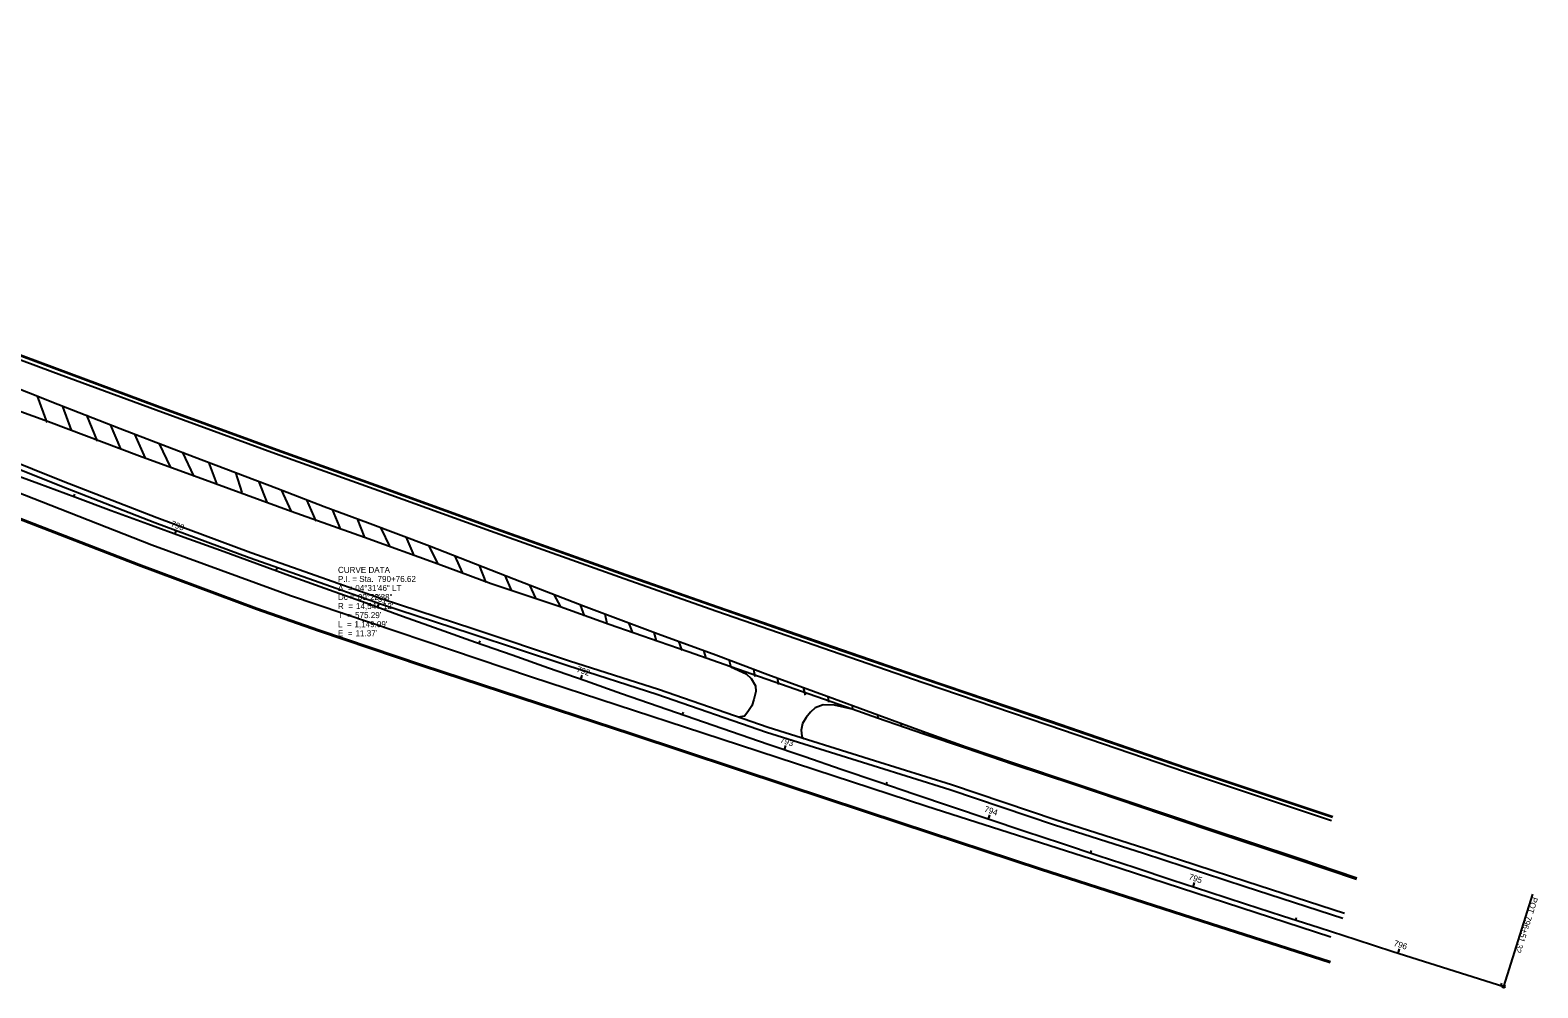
# Model space of a CAD drawing. Extents: x 2349621 to 2352073, y 625611 to 626553.
# Drawn here: x 2351373 to 2352073, y 625611 to 626056 of the extents above; entities that cross this region are included whole.
import ezdxf

# ---------------------------------------------------------------- set-up
doc = ezdxf.new("R2010")
doc.units = 0
for name, color, linetype in [('PM_X_Edge_Line', 7, 'Continuous'), ('PM_X_Lane_Line', 7, 'Continuous'), ('PV_X_Curb', 7, 'Continuous'), ('PV_X_EOP', 7, 'Continuous'), ('RW_X_CL', 7, 'Continuous'), ('RW_X_CL_1000_Cardinal_Points', 7, 'Continuous'), ('RW_X_CL_1000_Curve_Data', 7, 'Continuous'), ('RW_X_CL_1000_Stations', 7, 'Continuous'), ('RW_X_CL_100_Cardinal_Points', 7, 'Continuous'), ('RW_X_CL_100_Curve_Data', 7, 'Continuous'), ('RW_X_CL_100_Stations', 7, 'Continuous'), ('RW_X_CL_500_Cardinal_Points', 7, 'Continuous'), ('RW_X_CL_500_Curve_Data', 7, 'Continuous'), ('RW_X_CL_500_Stations', 7, 'Continuous')]:
    doc.layers.add(name, color=color, linetype=linetype)

msp = doc.modelspace()

# ---------------------------------------------------------------- linework, layer by layer
at = {"layer": 'PM_X_Edge_Line'}
for p, q in [((2351376.36, 625885.73), (2351380.84, 625873.57)), ((2351388.04, 625880.99), (2351392.18, 625870)), ((2351399.17, 625876.89), (2351404.23, 625864.91)), ((2351410.14, 625872.65), (2351414.94, 625861.28)), ((2351421.47, 625868.05), (2351426.41, 625857.03)), ((2351432.72, 625864), (2351438.15, 625852.68)), ((2351443.65, 625859.86), (2351448.97, 625848.49)), ((2351455.76, 625855.15), (2351459.52, 625845.23)), ((2351468.31, 625850.27), (2351471.33, 625841.06)), ((2351479.08, 625846.31), (2351482.87, 625836.48)), ((2351489.61, 625842.24), (2351494.17, 625832.3)), ((2351501.33, 625837.59), (2351505.6, 625827.67)), ((2351513.12, 625833.11), (2351517.13, 625823.81)), ((2351524.78, 625828.8), (2351528.25, 625820.22)), ((2351535.83, 625824.52), (2351539.96, 625815.78)), ((2351547.42, 625820.43), (2351551.12, 625811.83)), ((2351558.03, 625816.33), (2351562.27, 625807.85)), ((2351570.16, 625811.41), (2351573.43, 625803.84)), ((2351581.46, 625807.23), (2351584.55, 625799.22)), ((2351593.27, 625802.55), (2351596.23, 625795.72)), ((2351604.81, 625797.97), (2351607.53, 625792.05)), ((2351616.08, 625793.71), (2351619.08, 625787.98)), ((2351628.32, 625788.84), (2351630.09, 625783.85)), ((2351639.62, 625784.73), (2351640.66, 625780.21)), ((2351650.79, 625780.26), (2351652.47, 625775.89)), ((2351662.44, 625776.12), (2351663.45, 625772.26)), ((2351673.87, 625772.01), (2351675.4, 625767.7)), ((2351685.5, 625767.67), (2351686.61, 625764.06)), ((2351697.43, 625763.07), (2351697.97, 625760.51)), ((2351708.69, 625758.97), (2351709.31, 625755.61)), ((2351719.62, 625754.94), (2351720.29, 625751.98)), ((2351731.66, 625750.47), (2351732.57, 625746.94)), ((2351743.22, 625746.25), (2351743.45, 625743.64)), ((2351754.44, 625742.14), (2351754.65, 625740.35)), ((2351766.12, 625737.97), (2351766.34, 625736.14)), ((2351776.99, 625733.9), (2351777.4, 625732.36)), ((2351787.52, 625730.01), (2351787.61, 625728.96))]:
    msp.add_line(p, q, dxfattribs=at)
for points in [[(2350977.47, 626053.74), (2351016.31, 626038.35), (2351064.02, 626019.46), (2351106.89, 626002.49), (2351147.94, 625986.36), (2351202.99, 625965.26), (2351234.48, 625953.25), (2351287.27, 625933.36), (2351341.06, 625912.89), (2351383.66, 625897.13), (2351431.5, 625879.43), (2351486.97, 625859.09), (2351534.91, 625841.93), (2351586.59, 625823.19), (2351648.67, 625801.11), (2351691.59, 625785.98), (2351744.85, 625767.54), (2351787.37, 625752.87), (2351845.28, 625733.19), (2351909.09, 625711.34), (2351976.75, 625688.75)], [(2350963.74, 626014.89), (2351032.32, 625987.17), (2351095.71, 625962.07), (2351152.54, 625939.23), (2351209.68, 625916.15), (2351265.03, 625893.7), (2351303.58, 625877.76), (2351345.44, 625860.89), (2351387.6, 625843.99), (2351430.99, 625827.11), (2351474.75, 625810.9), (2351502.4, 625801.12), (2351535.69, 625789.35), (2351577.68, 625775.6), (2351622.58, 625760.66), (2351663.85, 625747.4), (2351714.74, 625729.84), (2351764.19, 625714.28), (2351799.77, 625703.13), (2351848.31, 625686.82), (2351889.58, 625673.56), (2351936.76, 625658.21), (2351982.15, 625643.49)], [(2351976.42, 625623.21), (2351920.83, 625640.97), (2351841.95, 625666.41), (2351777.12, 625687.69), (2351724.25, 625705.24), (2351652.33, 625728.98), (2351591.84, 625748.83), (2351555.08, 625760.87), (2351507.03, 625777.09), (2351478.29, 625787.21), (2351423.53, 625807.58), (2351365.19, 625830.22), (2351304.85, 625854.49), (2351247.93, 625877.37), (2351203.89, 625894.92), (2351143.43, 625919.65), (2351117.74, 625929.97), (2351079.36, 625945.33), (2351042.9, 625960.12), (2351003.33, 625976.06), (2350965.81, 625991.28), (2350956.45, 625995.04)], [(2351344.1, 625898.66), (2351385.94, 625881.99), (2351414.84, 625870.78), (2351449.22, 625857.66), (2351487.58, 625843.02), (2351509.43, 625834.57), (2351529.62, 625827.1), (2351558.41, 625816.34), (2351597.42, 625801.03), (2351629.84, 625788.39), (2351664.5, 625775.46), (2351691.21, 625765.65), (2351715.27, 625756.61), (2351746.28, 625745.26), (2351766.86, 625737.73), (2351788.72, 625729.58), (2351807.32, 625722.96), (2351829.82, 625715.37), (2351857.47, 625706.1), (2351919.67, 625685.17), (2351961.16, 625671.41), (2351988.6, 625662.13)]]:
    msp.add_lwpolyline(points, dxfattribs=at)
at = {"layer": 'PM_X_Lane_Line'}
msp.add_lwpolyline([(2350960.41, 626005.5), (2351002.64, 625988.3), (2351066, 625962.88), (2351136.34, 625934.22), (2351210.8, 625903.65), (2351315.64, 625861.8), (2351357.25, 625845.01), (2351429.58, 625816.81), (2351493.91, 625793.24), (2351605.6, 625755.44), (2351685.16, 625729.5), (2351789.05, 625695.46), (2351865.04, 625671.13), (2351976.54, 625634.71)], dxfattribs=at)
at = {"layer": 'PV_X_Curb'}
msp.add_lwpolyline([(2350978.14, 626055.68), (2351017.07, 626040.25), (2351064.77, 626021.37), (2351107.64, 626004.39), (2351148.68, 625988.27), (2351203.72, 625967.18), (2351235.21, 625955.17), (2351288, 625935.28), (2351341.78, 625914.81), (2351384.37, 625899.05), (2351432.2, 625881.35), (2351487.67, 625861.02), (2351535.61, 625843.86), (2351587.29, 625825.12), (2351649.36, 625803.04), (2351692.27, 625787.92), (2351745.52, 625769.48), (2351788.03, 625754.81), (2351845.94, 625735.13), (2351909.74, 625713.28), (2351977.4, 625690.7)], dxfattribs=at)
at = {"layer": 'PV_X_EOP'}
for points in [[(2351977.24, 625690.22), (2351909.58, 625712.81), (2351845.78, 625734.65), (2351787.87, 625754.34), (2351745.36, 625769.01), (2351692.1, 625787.45), (2351649.19, 625802.57), (2351587.12, 625824.65), (2351535.44, 625843.39), (2351487.5, 625860.55), (2351432.03, 625880.88), (2351384.2, 625898.58), (2351341.6, 625914.34), (2351287.82, 625934.81), (2351235.03, 625954.7), (2351203.54, 625966.71), (2351148.5, 625987.81), (2351107.45, 626003.93), (2351064.59, 626020.91), (2351016.88, 626039.79), (2350977.96, 626055.22)], [(2351982.85, 625645.63), (2351937.46, 625660.36), (2351890.28, 625675.71), (2351849.01, 625688.96), (2351800.47, 625705.27), (2351764.87, 625716.44), (2351715.44, 625731.98), (2351664.57, 625749.54), (2351623.28, 625762.81), (2351578.39, 625777.74), (2351536.41, 625791.49), (2351503.15, 625803.24), (2351475.52, 625813.02), (2351431.79, 625829.22), (2351388.43, 625846.09), (2351346.28, 625862.98), (2351304.44, 625879.85), (2351265.89, 625895.79), (2351210.53, 625918.24), (2351153.38, 625941.32), (2351096.55, 625964.17), (2351033.16, 625989.26), (2350964.49, 626017.02)], [(2351976.27, 625622.73), (2351920.68, 625640.49), (2351841.8, 625665.93), (2351776.97, 625687.21), (2351724.09, 625704.77), (2351652.18, 625728.51), (2351591.68, 625748.36), (2351554.93, 625760.4), (2351506.86, 625776.62), (2351478.12, 625786.74), (2351423.35, 625807.11), (2351365, 625829.75), (2351304.66, 625854.02), (2351247.74, 625876.9), (2351203.71, 625894.46), (2351143.24, 625919.19), (2351117.55, 625929.5), (2351079.17, 625944.86), (2351042.71, 625959.65), (2351003.14, 625975.6), (2350965.62, 625990.82), (2350956.27, 625994.57)], [(2351988.37, 625661.45), (2351960.93, 625670.74), (2351919.45, 625684.49), (2351857.24, 625705.43), (2351829.59, 625714.69), (2351807.08, 625722.29), (2351787.66, 625728.93), (2351766.19, 625736.23), (2351754.38, 625740.42), (2351698.18, 625760.06), (2351678.43, 625767), (2351664.88, 625771.73), (2351641.72, 625779.77), (2351618.91, 625787.9), (2351586.99, 625798.6), (2351562.33, 625807.73), (2351528.25, 625820.2), (2351494.14, 625832.28), (2351459.11, 625845.08), (2351423.86, 625857.97), (2351381.54, 625873.89), (2351346.84, 625886.35)], [(2351698.18, 625760.06), (2351705.3, 625756.82), (2351707.63, 625754.77), (2351709.58, 625751.23), (2351709.69, 625748.61), (2351708.88, 625744.9), (2351707.89, 625742.03), (2351706.07, 625739.26), (2351704.43, 625737.23), (2351701.75, 625736.68)], [(2351754.38, 625740.42), (2351746.22, 625742.39), (2351740.94, 625742.49), (2351737.35, 625741.14), (2351735.18, 625739.09), (2351733.13, 625736.65), (2351731.37, 625733.73), (2351730.85, 625730.73), (2351731.14, 625727.86), (2351732.08, 625726.71)]]:
    msp.add_lwpolyline(points, dxfattribs=at)
at = {"layer": 'RW_X_CL'}
msp.add_arc((2356442.68, 639481.86), 14547.12, 247.922783, 252.452173, dxfattribs=at)
at = {"layer": 'RW_X_CL_1000_Cardinal_Points'}
msp.add_line((2352056.7, 625611.68), (2352070.26, 625654.59), dxfattribs=at)
msp.add_circle((2352056.7, 625611.68), 0.6, dxfattribs=at)
at = {"layer": 'RW_X_CL_1000_Stations'}
for p, q in [((2351440.29, 625821.89), (2351440.98, 625823.77)), ((2351912.66, 625658.05), (2351913.03, 625659.19))]:
    msp.add_line(p, q, dxfattribs=at)
at = {"layer": 'RW_X_CL_100_Cardinal_Points'}
msp.add_line((2352056.7, 625611.68), (2352070.26, 625654.59), dxfattribs=at)
msp.add_circle((2352056.7, 625611.68), 0.6, dxfattribs=at)
at = {"layer": 'RW_X_CL_100_Stations'}
for p, q in [((2351393.37, 625839.16), (2351393.78, 625840.29)), ((2351440.29, 625821.89), (2351440.98, 625823.77)), ((2351487.27, 625804.78), (2351487.68, 625805.91)), ((2351534.31, 625787.83), (2351534.98, 625789.71)), ((2351581.4, 625771.04), (2351581.81, 625772.17)), ((2351628.56, 625754.41), (2351629.22, 625756.3)), ((2351675.77, 625737.94), (2351676.16, 625739.08)), ((2351723.04, 625721.64), (2351723.69, 625723.53)), ((2351770.36, 625705.5), (2351770.75, 625706.64)), ((2351817.74, 625689.52), (2351818.37, 625691.42)), ((2351865.17, 625673.71), (2351865.55, 625674.85)), ((2351912.66, 625658.05), (2351913.28, 625659.96)), ((2351960.2, 625642.57), (2351960.57, 625643.71)), ((2352007.79, 625627.24), (2352008.4, 625629.15)), ((2352055.44, 625612.08), (2352055.8, 625613.22))]:
    msp.add_line(p, q, dxfattribs=at)
at = {"layer": 'RW_X_CL_500_Cardinal_Points'}
msp.add_line((2352056.7, 625611.68), (2352070.26, 625654.59), dxfattribs=at)
msp.add_circle((2352056.7, 625611.68), 0.6, dxfattribs=at)
at = {"layer": 'RW_X_CL_500_Stations'}
for p, q in [((2351440.29, 625821.89), (2351440.98, 625823.77)), ((2351534.31, 625787.83), (2351534.71, 625788.96)), ((2351628.56, 625754.41), (2351628.96, 625755.54)), ((2351723.04, 625721.64), (2351723.43, 625722.77)), ((2351817.74, 625689.52), (2351818.12, 625690.66)), ((2351912.66, 625658.05), (2351913.28, 625659.96)), ((2352007.79, 625627.24), (2352008.16, 625628.38))]:
    msp.add_line(p, q, dxfattribs=at)

# ---------------------------------------------------------------- texts
at = {"layer": 'RW_X_CL_1000_Cardinal_Points'}
for s, p in [('POT', (2352069.97, 625653.5)), ('796+51.32', (2352067.22, 625644.79))]:
    msp.add_text(s, height=2.8, rotation=252.45217, dxfattribs=at).set_placement(p)
at = {"layer": 'RW_X_CL_1000_Curve_Data'}
for s, p in [('CURVE DATA', (2351515.88, 625803.72)), ('Δ  = ', (2351515.88, 625795.32)), ('P.I. = Sta. ', (2351515.88, 625799.52)), ('04°31\'46" LT', (2351523.9, 625795.32)), ('790+76.62', (2351534.25, 625799.52)), ('Dc = ', (2351515.88, 625791.12)), ('00°23\'38"', (2351525.12, 625791.12)), ('T  = ', (2351515.88, 625782.72)), ('R  = ', (2351515.88, 625786.92)), ("575.29'", (2351523.81, 625782.72)), ("14,547.12'", (2351524.25, 625786.92)), ('L  = ', (2351515.88, 625778.52)), ('E  = ', (2351515.88, 625774.32)), ("1,149.99'", (2351523.53, 625778.52)), ("11.37'", (2351524.03, 625774.32))]:
    msp.add_text(s, height=2.8, dxfattribs=at).set_placement(p)
at = {"layer": 'RW_X_CL_1000_Stations'}
msp.add_text('790', height=2.8, rotation=339.88686, dxfattribs=at).set_placement((2351438.08, 625825.41))
at = {"layer": 'RW_X_CL_100_Cardinal_Points'}
for s, p in [('POT', (2352069.97, 625653.5)), ('796+51.32', (2352067.22, 625644.79))]:
    msp.add_text(s, height=2.8, rotation=252.45217, dxfattribs=at).set_placement(p)
at = {"layer": 'RW_X_CL_100_Curve_Data'}
for s, p in [('CURVE DATA', (2351515.88, 625803.72)), ('Δ  = ', (2351515.88, 625795.32)), ('P.I. = Sta. ', (2351515.88, 625799.52)), ('04°31\'46" LT', (2351523.9, 625795.32)), ('790+76.62', (2351534.25, 625799.52)), ('Dc = ', (2351515.88, 625791.12)), ('00°23\'38"', (2351525.12, 625791.12)), ('T  = ', (2351515.88, 625782.72)), ('R  = ', (2351515.88, 625786.92)), ("575.29'", (2351523.81, 625782.72)), ("14,547.12'", (2351524.25, 625786.92)), ('L  = ', (2351515.88, 625778.52)), ('E  = ', (2351515.88, 625774.32)), ("1,149.99'", (2351523.53, 625778.52)), ("11.37'", (2351524.03, 625774.32))]:
    msp.add_text(s, height=2.8, dxfattribs=at).set_placement(p)
at = {"layer": 'RW_X_CL_100_Stations'}
for s, rotation, p in [('790', 339.88686, (2351438.08, 625825.41)), ('791', 340.28073, (2351532.24, 625791.27)), ('792', 340.67459, (2351626.31, 625757.9)), ('793', 341.06845, (2351720.78, 625725.11)), ('794', 341.46232, (2351815.48, 625692.97)), ('795', 341.85618, (2351910.32, 625661.5)), ('796', 342.25004, (2352005.44, 625630.67))]:
    msp.add_text(s, height=2.8, rotation=rotation, dxfattribs=at).set_placement(p)
at = {"layer": 'RW_X_CL_500_Cardinal_Points'}
for s, p in [('POT', (2352069.97, 625653.5)), ('796+51.32', (2352067.22, 625644.79))]:
    msp.add_text(s, height=2.8, rotation=252.45217, dxfattribs=at).set_placement(p)
at = {"layer": 'RW_X_CL_500_Curve_Data'}
for s, p in [('CURVE DATA', (2351515.88, 625803.72)), ('Δ  = ', (2351515.88, 625795.32)), ('P.I. = Sta. ', (2351515.88, 625799.52)), ('04°31\'46" LT', (2351523.9, 625795.32)), ('790+76.62', (2351534.25, 625799.52)), ('Dc = ', (2351515.88, 625791.12)), ('00°23\'38"', (2351525.12, 625791.12)), ('T  = ', (2351515.88, 625782.72)), ('R  = ', (2351515.88, 625786.92)), ("575.29'", (2351523.81, 625782.72)), ("14,547.12'", (2351524.25, 625786.92)), ('L  = ', (2351515.88, 625778.52)), ('E  = ', (2351515.88, 625774.32)), ("1,149.99'", (2351523.53, 625778.52)), ("11.37'", (2351524.03, 625774.32))]:
    msp.add_text(s, height=2.8, dxfattribs=at).set_placement(p)
at = {"layer": 'RW_X_CL_500_Stations'}
for s, rotation, p in [('790', 339.88686, (2351438.08, 625825.41)), ('795', 341.85618, (2351910.32, 625661.5))]:
    msp.add_text(s, height=2.8, rotation=rotation, dxfattribs=at).set_placement(p)

doc.saveas('drawing.dxf')
